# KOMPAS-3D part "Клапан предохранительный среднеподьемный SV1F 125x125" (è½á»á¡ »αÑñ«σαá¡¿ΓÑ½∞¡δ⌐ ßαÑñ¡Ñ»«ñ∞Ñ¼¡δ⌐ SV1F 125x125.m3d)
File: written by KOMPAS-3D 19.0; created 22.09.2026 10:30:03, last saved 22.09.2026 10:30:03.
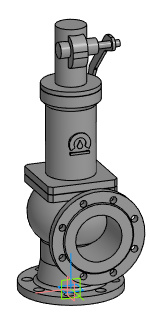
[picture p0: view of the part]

Document properties: Автор: Евгений; Полное имя файла: Z:\3.Личные\sachek\Dendor\_3D для проектировщиков\5.8 SV1F. Клапан предохранительный среднеподьемный\SV1F_STP\Клапан предохранительный среднеподьемный SV1F 125x125.m3d

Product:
- Part/product: Клапан предохранительный среднеподьемный SV1F 125x125
    Масса: 107.233

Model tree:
1. Операция без истории:1  (labels: Клапан предохранительный среднеподьемный SV1F 125x125)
